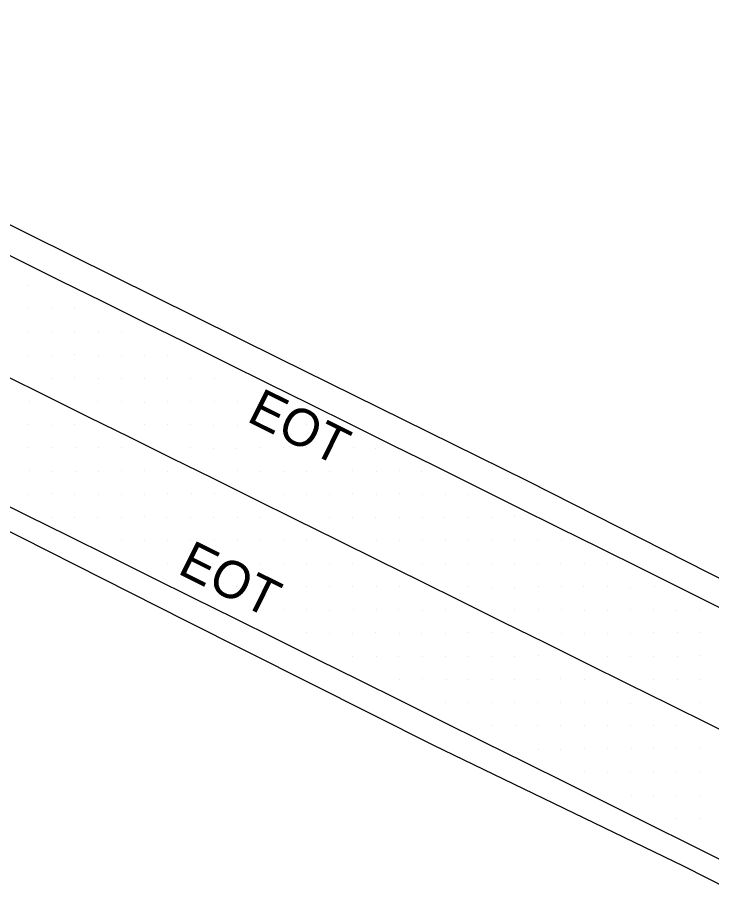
# Model space of a CAD drawing. Extents: x 2244337 to 2251208, y 199469 to 202984.
# Drawn here: x 2244710.3 to 2244785.3, y 202625.9 to 202719.2 of the extents above; entities that cross this region are included whole.
import ezdxf

# ---------------------------------------------------------------- set-up
doc = ezdxf.new("R2010")
doc.units = 0
for name, color, linetype in [('Exist DTM Scan Elevation Point', 7, 'Continuous'), ('Exist EOT Text', 7, 'Continuous'), ('Exist Roads EOP', 7, 'Continuous'), ('Exist Roads EOT', 7, 'Continuous')]:
    doc.layers.add(name, color=color, linetype=linetype)

msp = doc.modelspace()

# ---------------------------------------------------------------- linework, layer by layer
at = {"layer": 'Exist DTM Scan Elevation Point'}
for p, q in [((2244711.566, 202690.201), (2244711.566, 202690.201)), ((2244711.573, 202687.725), (2244711.573, 202687.725)), ((2244714.043, 202687.722), (2244714.043, 202687.722)), ((2244716.554, 202687.712), (2244716.554, 202687.712)), ((2244711.58, 202685.213), (2244711.58, 202685.213)), ((2244714.043, 202685.18), (2244714.043, 202685.18)), ((2244716.537, 202685.194), (2244716.537, 202685.194)), ((2244719.076, 202685.213), (2244719.076, 202685.213)), ((2244721.603, 202685.238), (2244721.603, 202685.238)), ((2244711.566, 202682.699), (2244711.566, 202682.699)), ((2244714.036, 202682.706), (2244714.036, 202682.706)), ((2244716.543, 202682.741), (2244716.543, 202682.741)), ((2244719.071, 202682.677), (2244719.071, 202682.677)), ((2244721.56, 202682.728), (2244721.56, 202682.728)), ((2244724.072, 202682.666), (2244724.072, 202682.666)), ((2244726.597, 202682.64), (2244726.597, 202682.64)), ((2244714.038, 202680.233), (2244714.038, 202680.233)), ((2244716.571, 202680.273), (2244716.571, 202680.273)), ((2244719.068, 202680.216), (2244719.068, 202680.216)), ((2244721.572, 202680.189), (2244721.572, 202680.189)), ((2244724.114, 202680.202), (2244724.114, 202680.202)), ((2244726.56, 202680.211), (2244726.56, 202680.211)), ((2244729.054, 202680.2), (2244729.054, 202680.2)), ((2244731.587, 202680.211), (2244731.587, 202680.211)), ((2244711.61, 202677.718), (2244711.61, 202677.718)), ((2244719.052, 202677.68), (2244719.052, 202677.68)), ((2244721.596, 202677.681), (2244721.596, 202677.681)), ((2244724.1, 202677.656), (2244724.1, 202677.656)), ((2244726.607, 202677.719), (2244726.607, 202677.719)), ((2244729.03, 202677.755), (2244729.03, 202677.755)), ((2244731.603, 202677.726), (2244731.603, 202677.726)), ((2244734.135, 202677.694), (2244734.135, 202677.694)), ((2244736.566, 202677.692), (2244736.566, 202677.692)), ((2244739.05, 202677.689), (2244739.05, 202677.689)), ((2244711.555, 202675.196), (2244711.555, 202675.196)), ((2244714.05, 202675.176), (2244714.05, 202675.176)), ((2244716.569, 202675.202), (2244716.569, 202675.202)), ((2244724.092, 202675.226), (2244724.092, 202675.226)), ((2244726.558, 202675.201), (2244726.558, 202675.201)), ((2244729.089, 202675.246), (2244729.089, 202675.246)), ((2244731.557, 202675.168), (2244731.557, 202675.168)), ((2244734.07, 202675.154), (2244734.07, 202675.154)), ((2244736.59, 202675.189), (2244736.59, 202675.189)), ((2244739.107, 202675.228), (2244739.107, 202675.228)), ((2244741.535, 202675.243), (2244741.535, 202675.243)), ((2244744.055, 202675.218), (2244744.055, 202675.218)), ((2244711.56, 202672.704), (2244711.56, 202672.704)), ((2244714.05, 202672.718), (2244714.05, 202672.718)), ((2244716.586, 202672.703), (2244716.586, 202672.703)), ((2244719.121, 202672.699), (2244719.121, 202672.699)), ((2244721.582, 202672.73), (2244721.582, 202672.73)), ((2244729.09, 202672.695), (2244729.09, 202672.695)), ((2244731.536, 202672.686), (2244731.536, 202672.686)), ((2244734.05, 202672.672), (2244734.05, 202672.672)), ((2244736.606, 202672.701), (2244736.606, 202672.701)), ((2244739.131, 202672.702), (2244739.131, 202672.702)), ((2244741.569, 202672.708), (2244741.569, 202672.708)), ((2244744.048, 202672.718), (2244744.048, 202672.718)), ((2244746.597, 202672.703), (2244746.597, 202672.703)), ((2244749.06, 202672.684), (2244749.06, 202672.684)), ((2244711.609, 202670.236), (2244711.609, 202670.236)), ((2244714.078, 202670.192), (2244714.078, 202670.192)), ((2244719.13, 202670.194), (2244719.13, 202670.194)), ((2244721.571, 202670.231), (2244721.571, 202670.231)), ((2244724.091, 202670.211), (2244724.091, 202670.211)), ((2244734.08, 202670.244), (2244734.08, 202670.244)), ((2244736.568, 202670.192), (2244736.568, 202670.192)), ((2244739.06, 202670.198), (2244739.06, 202670.198)), ((2244744.037, 202670.188), (2244744.037, 202670.188)), ((2244746.526, 202670.218), (2244746.526, 202670.218)), ((2244749.127, 202670.2), (2244749.127, 202670.2)), ((2244751.622, 202670.216), (2244751.622, 202670.216)), ((2244754.006, 202670.207), (2244754.006, 202670.207)), ((2244716.62, 202670.169), (2244716.62, 202670.169)), ((2244726.605, 202670.169), (2244726.605, 202670.169)), ((2244741.595, 202670.178), (2244741.595, 202670.178)), ((2244711.582, 202667.723), (2244711.582, 202667.723)), ((2244714.088, 202667.742), (2244714.088, 202667.742)), ((2244716.569, 202667.667), (2244716.569, 202667.667)), ((2244719.066, 202667.664), (2244719.066, 202667.664)), ((2244721.567, 202667.717), (2244721.567, 202667.717)), ((2244724.08, 202667.659), (2244724.08, 202667.659)), ((2244726.564, 202667.75), (2244726.564, 202667.75)), ((2244729.126, 202667.747), (2244729.126, 202667.747)), ((2244731.597, 202667.739), (2244731.597, 202667.739)), ((2244739.086, 202667.712), (2244739.086, 202667.712)), ((2244741.571, 202667.676), (2244741.571, 202667.676)), ((2244744.056, 202667.717), (2244744.056, 202667.717)), ((2244746.556, 202667.733), (2244746.556, 202667.733)), ((2244749.11, 202667.716), (2244749.11, 202667.716)), ((2244751.588, 202667.748), (2244751.588, 202667.748)), ((2244754.091, 202667.717), (2244754.091, 202667.717)), ((2244756.572, 202667.718), (2244756.572, 202667.718)), ((2244759.072, 202667.684), (2244759.072, 202667.684)), ((2244714.09, 202665.225), (2244714.09, 202665.225)), ((2244716.538, 202665.193), (2244716.538, 202665.193)), ((2244719.04, 202665.212), (2244719.04, 202665.212)), ((2244721.583, 202665.23), (2244721.583, 202665.23)), ((2244724.091, 202665.251), (2244724.091, 202665.251)), ((2244726.501, 202665.202), (2244726.501, 202665.202)), ((2244729.069, 202665.221), (2244729.069, 202665.221)), ((2244731.562, 202665.166), (2244731.562, 202665.166)), ((2244734.146, 202665.192), (2244734.146, 202665.192)), ((2244736.527, 202665.149), (2244736.527, 202665.149)), ((2244744.067, 202665.195), (2244744.067, 202665.195)), ((2244746.57, 202665.241), (2244746.57, 202665.241)), ((2244749.038, 202665.239), (2244749.038, 202665.239)), ((2244751.627, 202665.223), (2244751.627, 202665.223)), ((2244754.103, 202665.161), (2244754.103, 202665.161)), ((2244756.497, 202665.211), (2244756.497, 202665.211)), ((2244759.07, 202665.213), (2244759.07, 202665.213)), ((2244761.625, 202665.187), (2244761.625, 202665.187)), ((2244764.073, 202665.243), (2244764.073, 202665.243)), ((2244724.088, 202662.715), (2244724.088, 202662.715)), ((2244726.558, 202662.732), (2244726.558, 202662.732)), ((2244729.066, 202662.716), (2244729.066, 202662.716)), ((2244736.591, 202662.716), (2244736.591, 202662.716)), ((2244739.064, 202662.717), (2244739.064, 202662.717)), ((2244741.56, 202662.713), (2244741.56, 202662.713)), ((2244749.102, 202662.716), (2244749.102, 202662.716)), ((2244754.047, 202662.716), (2244754.047, 202662.716)), ((2244761.571, 202662.729), (2244761.571, 202662.729)), ((2244764.082, 202662.725), (2244764.082, 202662.725)), ((2244721.572, 202662.684), (2244721.572, 202662.684)), ((2244731.603, 202662.706), (2244731.603, 202662.706)), ((2244734.092, 202662.686), (2244734.092, 202662.686)), ((2244751.58, 202662.706), (2244751.58, 202662.706)), ((2244756.578, 202662.704), (2244756.578, 202662.704)), ((2244759.066, 202662.706), (2244759.066, 202662.706)), ((2244766.54, 202662.706), (2244766.54, 202662.706)), ((2244769.079, 202662.701), (2244769.079, 202662.701)), ((2244726.574, 202660.191), (2244726.574, 202660.191)), ((2244729.045, 202660.192), (2244729.045, 202660.192)), ((2244731.521, 202660.191), (2244731.521, 202660.191)), ((2244734.141, 202660.208), (2244734.141, 202660.208)), ((2244736.559, 202660.224), (2244736.559, 202660.224)), ((2244739.06, 202660.217), (2244739.06, 202660.217)), ((2244741.594, 202660.211), (2244741.594, 202660.211)), ((2244744.039, 202660.21), (2244744.039, 202660.21)), ((2244746.541, 202660.237), (2244746.541, 202660.237)), ((2244754.064, 202660.266), (2244754.064, 202660.266)), ((2244756.584, 202660.234), (2244756.584, 202660.234)), ((2244759.071, 202660.232), (2244759.071, 202660.232)), ((2244761.577, 202660.245), (2244761.577, 202660.245)), ((2244764.055, 202660.203), (2244764.055, 202660.203)), ((2244766.57, 202660.178), (2244766.57, 202660.178)), ((2244769.051, 202660.228), (2244769.051, 202660.228)), ((2244771.542, 202660.23), (2244771.542, 202660.23)), ((2244774.075, 202660.172), (2244774.075, 202660.172)), ((2244731.576, 202657.74), (2244731.576, 202657.74)), ((2244734.055, 202657.746), (2244734.055, 202657.746)), ((2244736.561, 202657.705), (2244736.561, 202657.705)), ((2244739.099, 202657.655), (2244739.099, 202657.655)), ((2244741.574, 202657.714), (2244741.574, 202657.714)), ((2244744.107, 202657.709), (2244744.107, 202657.709)), ((2244746.58, 202657.732), (2244746.58, 202657.732)), ((2244749.094, 202657.719), (2244749.094, 202657.719)), ((2244751.601, 202657.715), (2244751.601, 202657.715)), ((2244759.086, 202657.697), (2244759.086, 202657.697)), ((2244761.565, 202657.651), (2244761.565, 202657.651)), ((2244764.072, 202657.679), (2244764.072, 202657.679)), ((2244766.604, 202657.736), (2244766.604, 202657.736)), ((2244769.096, 202657.687), (2244769.096, 202657.687)), ((2244771.539, 202657.731), (2244771.539, 202657.731)), ((2244774.061, 202657.719), (2244774.061, 202657.719)), ((2244776.593, 202657.68), (2244776.593, 202657.68)), ((2244779.1, 202657.696), (2244779.1, 202657.696)), ((2244749.098, 202655.254), (2244749.098, 202655.254)), ((2244736.574, 202655.199), (2244736.574, 202655.199)), ((2244739.093, 202655.208), (2244739.093, 202655.208)), ((2244741.549, 202655.224), (2244741.549, 202655.224)), ((2244744.044, 202655.182), (2244744.044, 202655.182)), ((2244746.642, 202655.224), (2244746.642, 202655.224)), ((2244751.553, 202655.215), (2244751.553, 202655.215)), ((2244754.109, 202655.193), (2244754.109, 202655.193)), ((2244756.557, 202655.24), (2244756.557, 202655.24)), ((2244764.033, 202655.238), (2244764.033, 202655.238)), ((2244766.587, 202655.24), (2244766.587, 202655.24)), ((2244769.066, 202655.221), (2244769.066, 202655.221)), ((2244771.558, 202655.177), (2244771.558, 202655.177)), ((2244774.117, 202655.175), (2244774.117, 202655.175)), ((2244776.568, 202655.242), (2244776.568, 202655.242)), ((2244779.061, 202655.223), (2244779.061, 202655.223)), ((2244781.559, 202655.19), (2244781.559, 202655.19)), ((2244784.038, 202655.211), (2244784.038, 202655.211)), ((2244741.563, 202652.748), (2244741.563, 202652.748)), ((2244744.1, 202652.7), (2244744.1, 202652.7)), ((2244746.583, 202652.702), (2244746.583, 202652.702)), ((2244749.075, 202652.724), (2244749.075, 202652.724)), ((2244751.573, 202652.672), (2244751.573, 202652.672)), ((2244754.046, 202652.695), (2244754.046, 202652.695)), ((2244756.575, 202652.699), (2244756.575, 202652.699)), ((2244759.074, 202652.719), (2244759.074, 202652.719)), ((2244761.58, 202652.723), (2244761.58, 202652.723)), ((2244769.105, 202652.692), (2244769.105, 202652.692)), ((2244771.609, 202652.691), (2244771.609, 202652.691)), ((2244774.076, 202652.673), (2244774.076, 202652.673)), ((2244776.552, 202652.712), (2244776.552, 202652.712)), ((2244779.088, 202652.748), (2244779.088, 202652.748)), ((2244781.586, 202652.748), (2244781.586, 202652.748)), ((2244784.072, 202652.722), (2244784.072, 202652.722)), ((2244746.566, 202650.195), (2244746.566, 202650.195)), ((2244749.088, 202650.218), (2244749.088, 202650.218)), ((2244751.562, 202650.23), (2244751.562, 202650.23)), ((2244754.066, 202650.205), (2244754.066, 202650.205)), ((2244756.589, 202650.213), (2244756.589, 202650.213)), ((2244759.098, 202650.224), (2244759.098, 202650.224)), ((2244761.582, 202650.226), (2244761.582, 202650.226)), ((2244764.078, 202650.165), (2244764.078, 202650.165)), ((2244766.578, 202650.239), (2244766.578, 202650.239)), ((2244774.063, 202650.208), (2244774.063, 202650.208)), ((2244776.539, 202650.208), (2244776.539, 202650.208)), ((2244779.027, 202650.229), (2244779.027, 202650.229)), ((2244781.601, 202650.186), (2244781.601, 202650.186)), ((2244784.103, 202650.243), (2244784.103, 202650.243)), ((2244751.598, 202647.702), (2244751.598, 202647.702)), ((2244754.049, 202647.775), (2244754.049, 202647.775)), ((2244756.674, 202647.66), (2244756.674, 202647.66)), ((2244759.071, 202647.707), (2244759.071, 202647.707)), ((2244761.629, 202647.693), (2244761.629, 202647.693)), ((2244764.083, 202647.705), (2244764.083, 202647.705)), ((2244766.528, 202647.724), (2244766.528, 202647.724)), ((2244769.047, 202647.762), (2244769.047, 202647.762)), ((2244771.607, 202647.717), (2244771.607, 202647.717)), ((2244779.068, 202647.7), (2244779.068, 202647.7)), ((2244781.6, 202647.731), (2244781.6, 202647.731)), ((2244784.1, 202647.687), (2244784.1, 202647.687)), ((2244756.538, 202645.202), (2244756.538, 202645.202)), ((2244759.061, 202645.201), (2244759.061, 202645.201)), ((2244761.572, 202645.222), (2244761.572, 202645.222)), ((2244764.053, 202645.204), (2244764.053, 202645.204)), ((2244766.519, 202645.217), (2244766.519, 202645.217)), ((2244769.047, 202645.186), (2244769.047, 202645.186)), ((2244771.576, 202645.221), (2244771.576, 202645.221)), ((2244774.068, 202645.205), (2244774.068, 202645.205)), ((2244776.551, 202645.155), (2244776.551, 202645.155)), ((2244784.084, 202645.247), (2244784.084, 202645.247)), ((2244761.58, 202642.708), (2244761.58, 202642.708)), ((2244764.104, 202642.721), (2244764.104, 202642.721)), ((2244766.567, 202642.732), (2244766.567, 202642.732)), ((2244769.027, 202642.682), (2244769.027, 202642.682)), ((2244771.573, 202642.736), (2244771.573, 202642.736)), ((2244774.079, 202642.686), (2244774.079, 202642.686)), ((2244776.547, 202642.739), (2244776.547, 202642.739)), ((2244779.05, 202642.726), (2244779.05, 202642.726)), ((2244781.574, 202642.724), (2244781.574, 202642.724)), ((2244766.64, 202640.179), (2244766.64, 202640.179)), ((2244769.052, 202640.186), (2244769.052, 202640.186)), ((2244771.54, 202640.203), (2244771.54, 202640.203)), ((2244774.097, 202640.24), (2244774.097, 202640.24)), ((2244776.662, 202640.194), (2244776.662, 202640.194)), ((2244779.015, 202640.232), (2244779.015, 202640.232)), ((2244781.543, 202640.248), (2244781.543, 202640.248)), ((2244784.054, 202640.195), (2244784.054, 202640.195)), ((2244771.58, 202637.741), (2244771.58, 202637.741)), ((2244774.029, 202637.669), (2244774.029, 202637.669)), ((2244776.546, 202637.72), (2244776.546, 202637.72)), ((2244779.066, 202637.742), (2244779.066, 202637.742)), ((2244781.536, 202637.686), (2244781.536, 202637.686)), ((2244784.118, 202637.682), (2244784.118, 202637.682)), ((2244776.638, 202635.203), (2244776.638, 202635.203)), ((2244779.082, 202635.181), (2244779.082, 202635.181)), ((2244781.551, 202635.211), (2244781.551, 202635.211)), ((2244784.012, 202635.207), (2244784.012, 202635.207)), ((2244781.58, 202632.719), (2244781.58, 202632.719)), ((2244784.057, 202632.717), (2244784.057, 202632.717))]:
    msp.add_line(p, q, dxfattribs=at)
at = {"layer": 'Exist Roads EOP'}
for points in [[(2244351.85, 202873.142), (2244361.926, 202868.188), (2244388.909, 202855.071), (2244415.864, 202841.901), (2244442.667, 202828.422), (2244469.582, 202815.169), (2244496.518, 202801.951), (2244523.456, 202788.755), (2244550.257, 202775.265), (2244577.195, 202762.056), (2244604.107, 202748.802), (2244630.991, 202735.491), (2244657.923, 202722.281), (2244684.904, 202709.168), (2244711.728, 202695.726), (2244738.601, 202682.38), (2244765.504, 202669.1), (2244792.272, 202655.555), (2244819.231, 202642.393), (2244846.105, 202629.058), (2244872.909, 202615.582), (2244899.901, 202602.494), (2244926.632, 202588.876), (2244953.555, 202575.641)], [(2244943.481, 202547.284), (2244916.63, 202560.665), (2244889.679, 202573.825), (2244862.841, 202587.231), (2244835.877, 202600.401), (2244809.109, 202613.946), (2244782.35, 202627.512), (2244755.338, 202640.558), (2244728.535, 202654.036), (2244701.767, 202667.582), (2244674.669, 202680.464), (2244647.537, 202693.279), (2244620.757, 202706.793), (2244593.804, 202719.968), (2244566.899, 202733.237), (2244539.973, 202746.467), (2244513.27, 202760.093), (2244486.33, 202773.292), (2244459.378, 202786.533), (2244432.397, 202799.653), (2244405.408, 202812.754), (2244378.552, 202826.125), (2244351.631, 202839.366), (2244337.477, 202846.367)]]:
    msp.add_lwpolyline(points, dxfattribs=at)
at = {"layer": 'Exist Roads EOT'}
for points in [[(2244706.048, 202695.181), (2244710.532, 202692.97), (2244715.015, 202690.754), (2244719.497, 202688.539), (2244723.98, 202686.324), (2244728.462, 202684.108), (2244732.945, 202681.893), (2244737.427, 202679.677), (2244741.906, 202677.456), (2244746.386, 202675.234), (2244750.865, 202673.012), (2244755.344, 202670.79), (2244759.823, 202668.569), (2244764.303, 202666.347), (2244768.78, 202664.122), (2244773.258, 202661.897), (2244777.735, 202659.672), (2244782.213, 202657.447), (2244786.691, 202655.222)], [(2244709.042, 202680.511), (2244713.524, 202678.293), (2244718.005, 202676.075), (2244722.486, 202673.857), (2244726.967, 202671.639), (2244731.448, 202669.421), (2244735.93, 202667.203), (2244740.411, 202664.986), (2244744.892, 202662.768), (2244749.373, 202660.55), (2244753.854, 202658.332), (2244758.336, 202656.114), (2244762.817, 202653.896), (2244767.298, 202651.678), (2244771.779, 202649.46), (2244776.26, 202647.241), (2244780.741, 202645.023), (2244785.221, 202642.804), (2244789.702, 202640.585)], [(2244787.572, 202627.576), (2244783.097, 202629.806), (2244778.622, 202632.035), (2244774.145, 202634.263), (2244769.669, 202636.491), (2244765.19, 202638.714), (2244760.712, 202640.936), (2244756.233, 202643.159), (2244751.754, 202645.381), (2244747.275, 202647.604), (2244742.796, 202649.827), (2244738.317, 202652.049), (2244733.838, 202654.272), (2244729.359, 202656.494), (2244724.881, 202658.717), (2244720.402, 202660.939), (2244715.923, 202663.162), (2244711.444, 202665.384), (2244706.965, 202667.607)]]:
    msp.add_lwpolyline(points, dxfattribs=at)

# ---------------------------------------------------------------- texts
at = {"layer": 'Exist EOT Text'}
for rotation, p in [(333.62575, (2244735.001, 202675.637)), (333.65539, (2244727.525, 202659.203))]:
    msp.add_text('EOT', height=4.02, rotation=rotation, dxfattribs=at).set_placement(p)

doc.saveas('drawing.dxf')
